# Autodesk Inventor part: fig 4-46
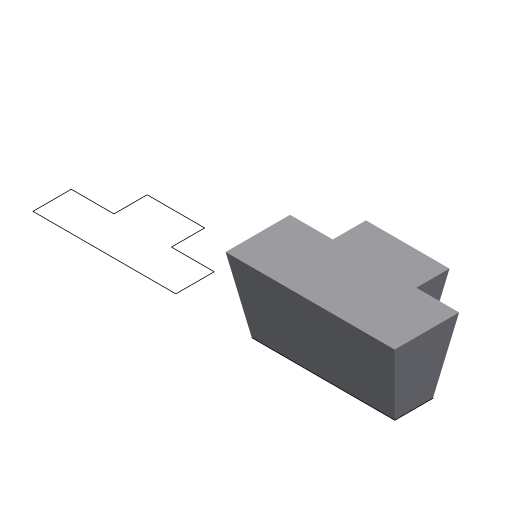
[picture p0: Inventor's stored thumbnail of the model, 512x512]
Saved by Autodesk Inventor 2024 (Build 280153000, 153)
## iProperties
Created: 2004-05
Part Number: fig 4-46
Document SubType Name: Modeling
Designer: CADCIM Technologies
Manufacturer: Standard
Standards Organization: Custom
Density: 1 g/cm^3
Material: Generic
Appearance: Default
Author: CADCIM Technologies
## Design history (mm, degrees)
sketch "Sketch1"
  geometry: L1 (31.783, 34.561)-(31.783, 22.933); L2 (31.783, 22.933)-(16.796, 22.933); L3 (16.796, 22.933)-(16.796, 9.496); L4 (16.796, 9.496)-(66.925, 9.496); L5 (66.925, 9.496)-(66.925, 22.933); L6 (66.925, 22.933)-(51.938, 22.933); L7 (51.938, 22.933)-(51.938, 34.561); L8 (51.938, 34.561)-(31.783, 34.561); L9 (-45.013, 34.561)-(-45.013, 22.933); L10 (-45.013, 22.933)-(-60, 22.933); L11 (-60, 22.933)-(-60, 9.496); L12 (-60, 9.496)-(-9.871, 9.496); L13 (-9.871, 9.496)-(-9.871, 22.933); L14 (-9.871, 22.933)-(-24.858, 22.933); L15 (-24.858, 22.933)-(-24.858, 34.561); L16 (-24.858, 34.561)-(-45.013, 34.561)
  constraints: 32 end point, 10 parallel, 4 equal length, 2 collinear, 2 perpendicular, 2 vertical
extrude "Extrusion2" new body sketch "Sketch1" distance "d2" = 26; taper "d3" = 10 deg
body "Solid2"
